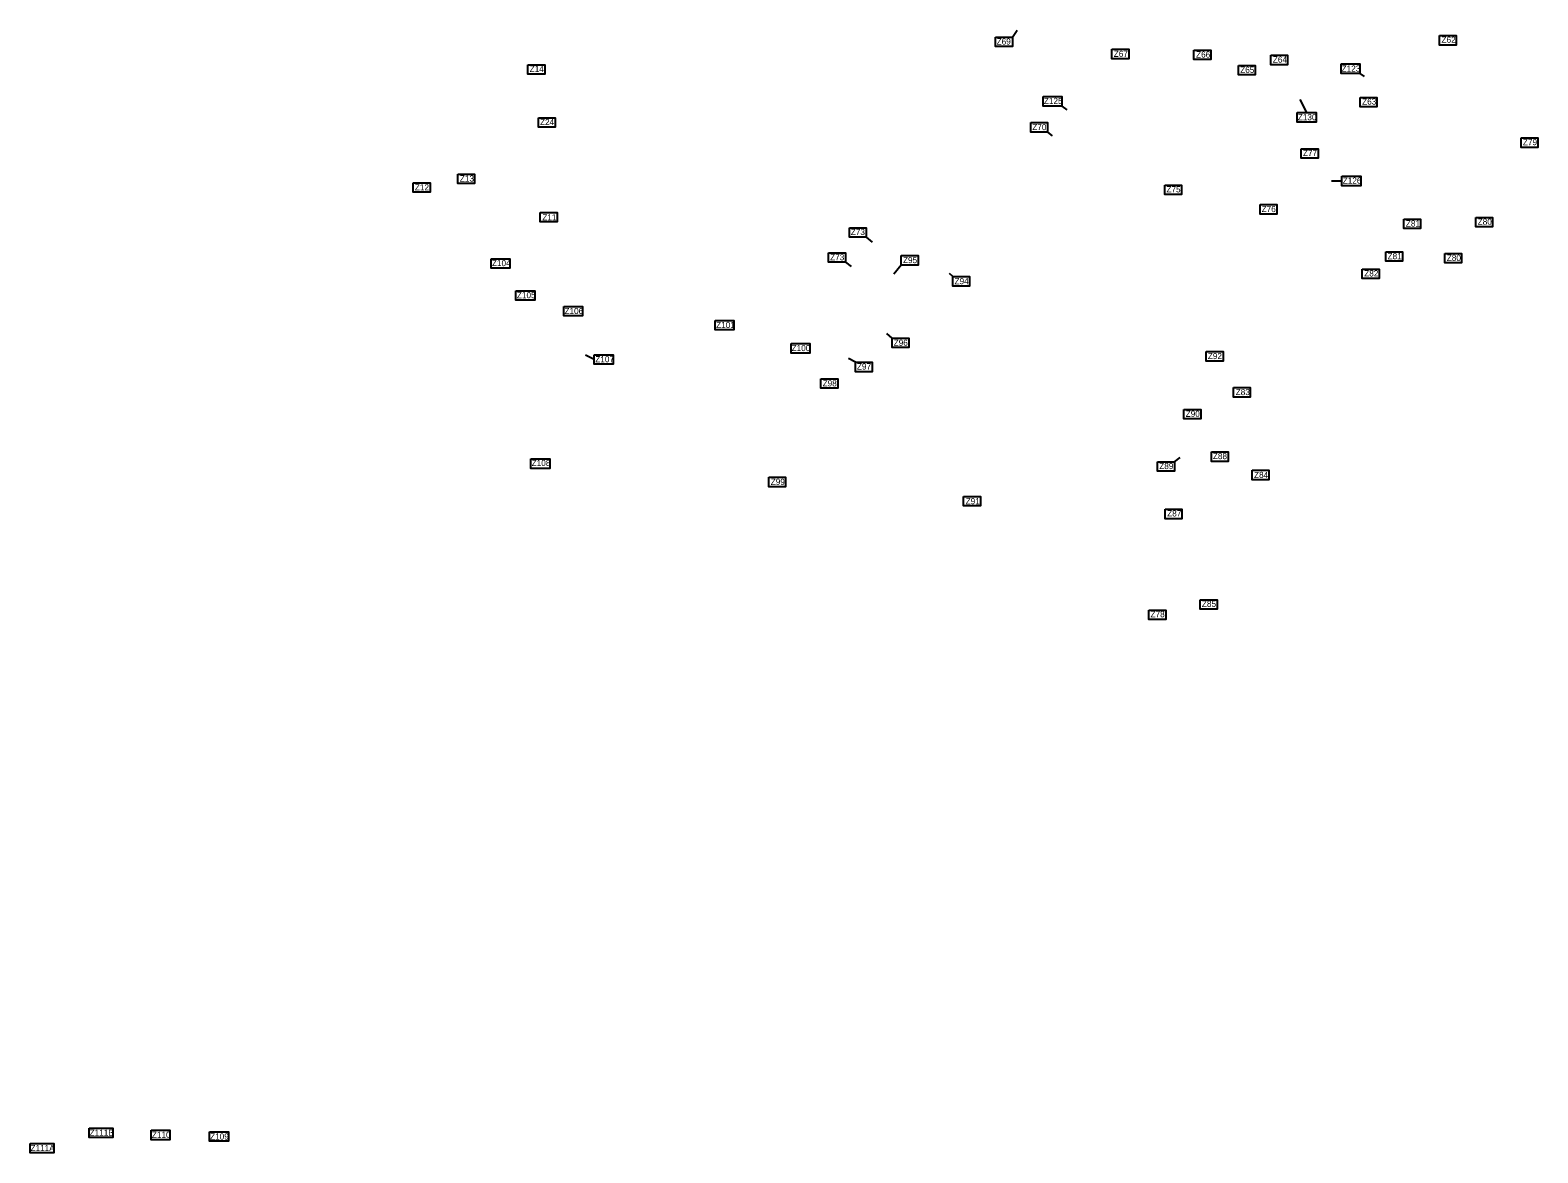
# Model space of a CAD drawing. Extents: x -443483 to -438119, y -1133472 to -1129797.
# Drawn here: x -443483 to -441026, y -1133472 to -1131641 of the extents above; entities that cross this region are included whole.
import ezdxf

# ---------------------------------------------------------------- set-up
doc = ezdxf.new("R2010")
doc.units = 0
doc.layers.add('Vrstva 3', color=7, linetype='Continuous')
doc.layers.add('Vrstva 8', color=7, linetype='Continuous')

msp = doc.modelspace()

# ---------------------------------------------------------------- linework, layer by layer
at = {"layer": 'Vrstva 3'}
for p, q in [((-441882.1, -1131652.8), (-441874.3, -1131641.5)), ((-441824.8, -1131807.6), (-441817.5, -1131813.7)), ((-442120.5, -1131979), (-442110.5, -1131987.2)), ((-442154.2, -1132019.9), (-442145, -1132026.9)), ((-442063.3, -1132024.4), (-442075.2, -1132039)), ((-441979.2, -1132043.3), (-441984.6, -1132037.9)), ((-442078.2, -1132143.6), (-442086.6, -1132135.9)), ((-442563.8, -1132178.3), (-442578.2, -1132171.1)), ((-442137.9, -1132182.9), (-442149.2, -1132176.8)), ((-441618.1, -1132344.9), (-441608.8, -1132338.2))]:
    msp.add_line(p, q, dxfattribs=at)
for points in [[(-441909.5, -1131652.8), (-441882.1, -1131652.8), (-441882.1, -1131668.2), (-441909.5, -1131668.2)], [(-441186, -1131650.3), (-441158.6, -1131650.3), (-441158.6, -1131665.7), (-441186, -1131665.7)], [(-441719.9, -1131672.7), (-441692.5, -1131672.7), (-441692.5, -1131688.1), (-441719.9, -1131688.1)], [(-441586.1, -1131673.9), (-441558.7, -1131673.9), (-441558.7, -1131689.3), (-441586.1, -1131689.3)], [(-441460.9, -1131682.5), (-441433.5, -1131682.5), (-441433.5, -1131697.9), (-441460.9, -1131697.9)], [(-442671.7, -1131697.8), (-442644.4, -1131697.8), (-442644.4, -1131713.2), (-442671.7, -1131713.2)], [(-441513.5, -1131699.1), (-441486.1, -1131699.1), (-441486.1, -1131714.5), (-441513.5, -1131714.5)], [(-441315.3, -1131751.1), (-441287.9, -1131751.1), (-441287.9, -1131766.5), (-441315.3, -1131766.5)], [(-442654.5, -1131784.2), (-442627.2, -1131784.2), (-442627.2, -1131799.6), (-442654.5, -1131799.6)], [(-441852.1, -1131792.2), (-441824.8, -1131792.2), (-441824.8, -1131807.6), (-441852.1, -1131807.6)], [(-441411.2, -1131834.7), (-441383.8, -1131834.7), (-441383.8, -1131850.1), (-441411.2, -1131850.1)], [(-441053, -1131817.2), (-441025.6, -1131817.2), (-441025.6, -1131832.6), (-441053, -1131832.6)], [(-442786.3, -1131876), (-442759, -1131876), (-442759, -1131891.4), (-442786.3, -1131891.4)], [(-442858.8, -1131890.4), (-442831.4, -1131890.4), (-442831.4, -1131905.8), (-442858.8, -1131905.8)], [(-441633.7, -1131893.9), (-441606.4, -1131893.9), (-441606.4, -1131909.3), (-441633.7, -1131909.3)], [(-442651.8, -1131938.6), (-442624.4, -1131938.6), (-442624.4, -1131954), (-442651.8, -1131954)], [(-441478.3, -1131925.9), (-441450.9, -1131925.9), (-441450.9, -1131941.3), (-441478.3, -1131941.3)], [(-441244, -1131949.4), (-441216.7, -1131949.4), (-441216.7, -1131964.8), (-441244, -1131964.8)], [(-441126.7, -1131946.9), (-441099.4, -1131946.9), (-441099.4, -1131962.3), (-441126.7, -1131962.3)], [(-442147.8, -1131963.6), (-442120.5, -1131963.6), (-442120.5, -1131979), (-442147.8, -1131979)], [(-442181.6, -1132004.5), (-442154.2, -1132004.5), (-442154.2, -1132019.9), (-442181.6, -1132019.9)], [(-442063.3, -1132009), (-442035.9, -1132009), (-442035.9, -1132024.4), (-442063.3, -1132024.4)], [(-441273.5, -1132002.7), (-441246.1, -1132002.7), (-441246.1, -1132018.1), (-441273.5, -1132018.1)], [(-441177.4, -1132005.6), (-441150, -1132005.6), (-441150, -1132021), (-441177.4, -1132021)], [(-442731.9, -1132014.2), (-442701.2, -1132014.2), (-442701.2, -1132029.6), (-442731.9, -1132029.6)], [(-441311.8, -1132031.1), (-441284.4, -1132031.1), (-441284.4, -1132046.5), (-441311.8, -1132046.5)], [(-441979.2, -1132043.3), (-441951.9, -1132043.3), (-441951.9, -1132058.7), (-441979.2, -1132058.7)], [(-442691.5, -1132066.2), (-442660.7, -1132066.2), (-442660.7, -1132081.6), (-442691.5, -1132081.6)], [(-442613.5, -1132092), (-442582.8, -1132092), (-442582.8, -1132107.4), (-442613.5, -1132107.4)], [(-442366.7, -1132114.8), (-442336, -1132114.8), (-442336, -1132130.2), (-442366.7, -1132130.2)], [(-442242.9, -1132152.5), (-442212.2, -1132152.5), (-442212.2, -1132167.9), (-442242.9, -1132167.9)], [(-442078.2, -1132143.6), (-442050.9, -1132143.6), (-442050.9, -1132159), (-442078.2, -1132159)], [(-442563.8, -1132170.6), (-442533.1, -1132170.6), (-442533.1, -1132186), (-442563.8, -1132186)], [(-442137.9, -1132182.9), (-442110.5, -1132182.9), (-442110.5, -1132198.2), (-442137.9, -1132198.2)], [(-441566, -1132165.5), (-441538.6, -1132165.5), (-441538.6, -1132180.9), (-441566, -1132180.9)], [(-442194.3, -1132209.9), (-442166.9, -1132209.9), (-442166.9, -1132225.3), (-442194.3, -1132225.3)], [(-441521.7, -1132224.2), (-441494.3, -1132224.2), (-441494.3, -1132239.6), (-441521.7, -1132239.6)], [(-441602.6, -1132259.7), (-441575.2, -1132259.7), (-441575.2, -1132275.1), (-441602.6, -1132275.1)], [(-441557.5, -1132329), (-441530.2, -1132329), (-441530.2, -1132344.4), (-441557.5, -1132344.4)], [(-442667.1, -1132340.5), (-442636.3, -1132340.5), (-442636.3, -1132355.9), (-442667.1, -1132355.9)], [(-441645.5, -1132344.9), (-441618.1, -1132344.9), (-441618.1, -1132360.3), (-441645.5, -1132360.3)], [(-442279.2, -1132370.4), (-442251.8, -1132370.4), (-442251.8, -1132385.8), (-442279.2, -1132385.8)], [(-441491.3, -1132358.9), (-441463.9, -1132358.9), (-441463.9, -1132374.3), (-441491.3, -1132374.3)], [(-441961.6, -1132401.7), (-441934.2, -1132401.7), (-441934.2, -1132417.1), (-441961.6, -1132417.1)], [(-441633.2, -1132422.4), (-441605.8, -1132422.4), (-441605.8, -1132437.8), (-441633.2, -1132437.8)], [(-441575.8, -1132570.2), (-441548.5, -1132570.2), (-441548.5, -1132585.5), (-441575.8, -1132585.5)], [(-441659.5, -1132587.1), (-441632.1, -1132587.1), (-441632.1, -1132602.4), (-441659.5, -1132602.4)], [(-443387, -1133431.3), (-443348.5, -1133431.3), (-443348.5, -1133446.7), (-443387, -1133446.7)], [(-443286.1, -1133434.8), (-443255.3, -1133434.8), (-443255.3, -1133450.2), (-443286.1, -1133450.2)], [(-443190.7, -1133437.1), (-443160, -1133437.1), (-443160, -1133452.5), (-443190.7, -1133452.5)], [(-443483.2, -1133456.1), (-443444.8, -1133456.1), (-443444.8, -1133471.5), (-443483.2, -1133471.5)]]:
    msp.add_lwpolyline(points, close=True, dxfattribs=at)
at = {"layer": 'Vrstva 8'}
for p, q in [((-441315.6, -1131712), (-441308.9, -1131717.3)), ((-441801.4, -1131765.3), (-441793.1, -1131771.6)), ((-441402.4, -1131775.9), (-441412.9, -1131754.3)), ((-441345, -1131887.4), (-441361.9, -1131887.4))]:
    msp.add_line(p, q, dxfattribs=at)
for points in [[(-441346.4, -1131696.6), (-441315.6, -1131696.6), (-441315.6, -1131712), (-441346.4, -1131712)], [(-441832.2, -1131749.9), (-441801.4, -1131749.9), (-441801.4, -1131765.3), (-441832.2, -1131765.3)], [(-441417.8, -1131775.9), (-441387.1, -1131775.9), (-441387.1, -1131791.3), (-441417.8, -1131791.3)], [(-441345, -1131879.7), (-441314.2, -1131879.7), (-441314.2, -1131895.1), (-441345, -1131895.1)]]:
    msp.add_lwpolyline(points, close=True, dxfattribs=at)

# ---------------------------------------------------------------- texts
at = {"layer": 'Vrstva 3'}
for s, p in [('Z69', (-441907.8, -1131665)), ('Z62', (-441182.6, -1131662.1)), ('Z67', (-441716.9, -1131685)), ('Z66', (-441582.7, -1131686.2)), ('Z64', (-441457.5, -1131694.4)), ('Z14', (-442668.9, -1131709.6)), ('Z65', (-441510.7, -1131711.2)), ('Z63', (-441311.9, -1131762.9)), ('Z24', (-442652.1, -1131796.3)), ('Z70', (-441849.7, -1131804.5)), ('Z77', (-441408.5, -1131846.7)), ('Z79', (-441049.9, -1131829)), ('Z13', (-442782.8, -1131888.3)), ('Z12', (-442856.1, -1131902.7)), ('Z75', (-441631, -1131906)), ('Z76', (-441475.8, -1131938.1)), ('Z11', (-442648.3, -1131951.5)), ('Z81', (-441240.7, -1131961.6)), ('Z80', (-441123.6, -1131958.7)), ('Z73', (-442145.5, -1131975.5)), ('Z73', (-442179.2, -1132016.6)), ('Z95', (-442060.4, -1132021.3)), ('Z81', (-441270.5, -1132014.9)), ('Z80', (-441174, -1132017.7)), ('Z104', (-442730.5, -1132026.2)), ('Z82', (-441308.6, -1132043)), ('Z94', (-441976.4, -1132055.7)), ('Z105', (-442689.8, -1132078.4)), ('Z106', (-442612.2, -1132104.3)), ('Z101', (-442365, -1132127)), ('Z100', (-442242, -1132164.7)), ('Z96', (-442075.6, -1132156)), ('Z107', (-442562, -1132182.9)), ('Z92', (-441563.5, -1132177.7)), ('Z97', (-442135.5, -1132194.7)), ('Z98', (-442191.4, -1132222.2)), ('Z83', (-441518.1, -1132236.4)), ('Z90', (-441599.6, -1132271.8)), ('Z88', (-441555.3, -1132340.8)), ('Z108', (-442665.7, -1132352)), ('Z89', (-441642.7, -1132357)), ('Z99', (-442276, -1132382.7)), ('Z84', (-441488.2, -1132371.5)), ('Z91', (-441958.3, -1132414.3)), ('Z87', (-441629.8, -1132434.2)), ('Z85', (-441573.2, -1132581.6)), ('Z78', (-441656.9, -1132598.5)), ('Z111B', (-443386.3, -1133443.6)), ('Z110', (-443284.8, -1133447.1)), ('Z111A', (-443482.6, -1133468.7)), ('Z109', (-443189.9, -1133449.9))]:
    msp.add_text(s, height=10, dxfattribs=at).set_placement(p)
at = {"layer": 'Vrstva 8'}
for s, p in [('Z123', (-441345.4, -1131709.1)), ('Z125', (-441830.8, -1131761.9)), ('Z130', (-441416.9, -1131788.4)), ('Z126', (-441343.6, -1131891.7))]:
    msp.add_text(s, height=10, dxfattribs=at).set_placement(p)

doc.saveas('drawing.dxf')
